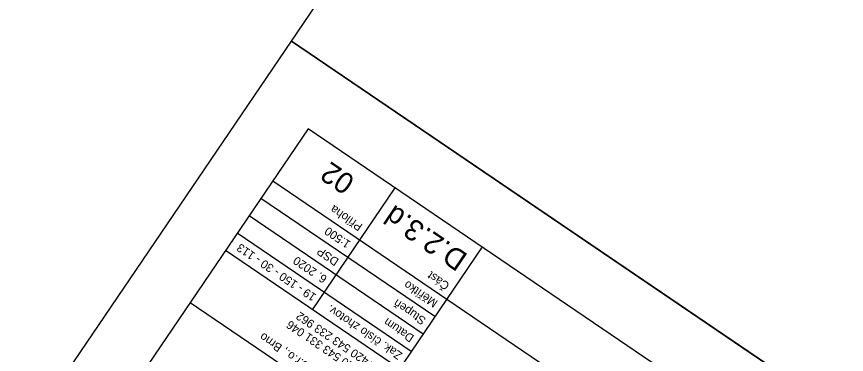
# Model space of a CAD drawing. Extents: x -621145 to -620110, y -1122807 to -1121971.
# Drawn here: x -621094.2 to -620995.6, y -1122131.1 to -1122091 of the extents above; entities that cross this region are included whole.
import ezdxf

# ---------------------------------------------------------------- set-up
doc = ezdxf.new("R2010")
doc.units = 0
for name, color, linetype in [('Ramečky', 7, 'Continuous'), ('RÁMY', 7, 'Continuous'), ('Text', 7, 'Continuous'), ('Text barevný', 7, 'Continuous')]:
    doc.layers.add(name, color=color, linetype=linetype)

msp = doc.modelspace()

# ---------------------------------------------------------------- linework, layer by layer
at = {"layer": 'Ramečky'}
for p, q in [((-621059.567, -1122104.336), (-621083.445, -1122139.495)), ((-620985.114, -1122154.9), (-621059.567, -1122104.336)), ((-620989.328, -1122161.105), (-621063.781, -1122110.541)), ((-621044.504, -1122126.654), (-621065.186, -1122112.609)), ((-621045.909, -1122128.722), (-621066.59, -1122114.677)), ((-621047.313, -1122130.791), (-621067.995, -1122116.745)), ((-621048.718, -1122132.859), (-621069.399, -1122118.813)), ((-621038.886, -1122118.382), (-621062.763, -1122153.54))]:
    msp.add_line(p, q, dxfattribs=at)
for points in [[(-621059.058, -1122125.836), (-621049.227, -1122111.359)], [(-621052.931, -1122139.063), (-621073.613, -1122125.018)]]:
    msp.add_lwpolyline(points, dxfattribs=at)
at = {"layer": 'RÁMY'}
for points in [[(-620978.128, -1121971.07), (-620891.265, -1122030.061), (-620974.696, -1122152.909), (-621061.558, -1122093.918)], [(-621061.558, -1122093.918), (-620192.937, -1122683.831), (-620276.367, -1122806.679), (-621144.989, -1122216.766)]]:
    msp.add_lwpolyline(points, close=True, dxfattribs=at)

# ---------------------------------------------------------------- texts
at = {"layer": 'Text'}
for s, p in [('Příloha', (-621053.015, -1122115.736)), ('1:500', (-621054.42, -1122117.805)), ('19 - 150 - 30 - 113', (-621058.519, -1122124.087)), ('DSP', (-621055.825, -1122119.873)), ('6. 2020', (-621057.229, -1122121.941)), ('Část', (-621042.675, -1122122.759)), ('Měřítko', (-621044.079, -1122124.827)), ('Stupeň', (-621045.484, -1122126.895)), ('Zak. číslo zhotov.', (-621048.293, -1122131.032)), ('tel: +420 543 233 962', (-621049.83, -1122133.312)), ('Datum', (-621046.888, -1122128.964)), ('fax: +420 543 331 046', (-621050.673, -1122134.553)), ('Signal Projekt s.r.o., Brno', (-621052.366, -1122137.03))]:
    msp.add_text(s, height=1, rotation=145.81812, dxfattribs=at).set_placement(p)
at = {"layer": 'Text barevný'}
for s, p in [('02', (-621053.86, -1122110.227)), ('D.2.3.d', (-621040.452, -1122119.333))]:
    msp.add_text(s, height=2.5, rotation=145.81812, dxfattribs=at).set_placement(p)

doc.saveas('drawing.dxf')
